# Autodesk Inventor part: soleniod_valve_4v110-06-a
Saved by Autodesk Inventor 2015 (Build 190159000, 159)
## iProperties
Created: 2018-08
Part Number: soleniod_valve_4v110-06-a
Checked By: TraceParts S.A.
Material: Generic
Catalog Web Link: www.traceparts.com
Document SubType Name: Modeling
Designer: TraceParts
Density: 1 g/cm^3
Appearance: Default
Company: TraceParts S.A.
Author: TraceParts
REFERENCE: 4V110-06-A
DESIGN: Soleniod Valve(5/2 way,5/3 way) 4V Series 4V110-06-A
SUPPLIER: ZheJiang XingChen pneumatic Co., LTD
TraceParts.PartNumber: 50-16072015-070146
TraceParts.PartTitle: Solenoid Valve(5/2 way,5/3 way) 4V Series
TraceParts.InstanceId: 50-16072015-0701465GDI1SPU4NASLYKM6WDY0ZWWY
TraceParts.PartStatus: Published
TraceParts.PartVersion: 1.2.0
TRACEPARTS: TRACEPARTS
TraceParts.PartLanguage: en
TraceParts.ClassPath: XINGCHEN_PNEUMATIC:/F_XINGCHEN_PNEUMATIC/XINGCHEN_PNEUMATIC.020/XINGCHEN_PNEUMATIC.020.010/50-16072015-070146
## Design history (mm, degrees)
feature "soleniod_valve_4v110-06-a"
body "Solid1"
